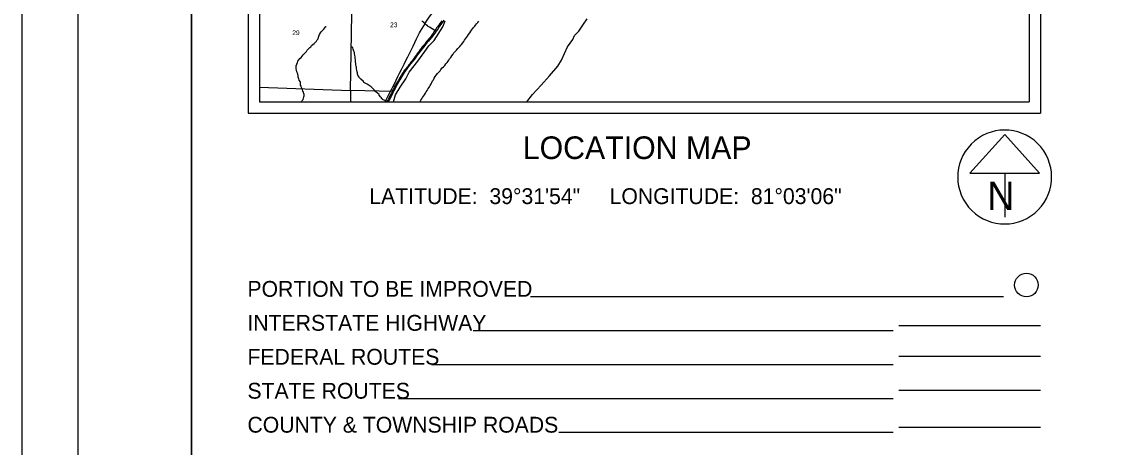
# Model space of a CAD drawing. Extents: x 6.3 to 40.3, y 9 to 31.
# Drawn here: x 6.34 to 15.93, y 20.09 to 23.85 of the extents above; entities that cross this region are included whole.
import ezdxf

# ---------------------------------------------------------------- set-up
doc = ezdxf.new("R2010")
doc.units = 0
for name, color, linetype in [('Default', 7, 'Continuous'), ('GM_X_Corporation', 7, 'Continuous'), ('GM_X_Major_River', 7, 'Continuous'), ('GM_X_Minor_River', 7, 'Continuous'), ('GM_X_Section', 7, 'Continuous'), ('GM_X_Section_Text', 7, 'Continuous'), ('GM_X_State_Route', 7, 'Continuous'), ('SH_Border', 7, 'Continuous'), ('SH_Cut_Line', 7, 'Continuous'), ('SH_Data', 7, 'Continuous'), ('SH_Text', 7, 'Continuous'), ('TX_P_1', 7, 'Continuous')]:
    doc.layers.add(name, color=color, linetype=linetype)

msp = doc.modelspace()

# ---------------------------------------------------------------- linework, layer by layer
at = {"layer": 'Default'}
for points in [[(8.4446, 29.2958), (8.4446, 23.1457), (9.6289, 23.1457), (9.6466, 23.2068), (9.687, 23.2757), (9.738, 23.3494), (9.7691, 23.406), (9.8432, 23.5031), (9.9069, 23.5887), (9.9412, 23.6381), (9.9898, 23.6859), (10.0659, 23.8074), (10.0861, 23.8612)], [(8.4446, 27.9161), (8.4446, 23.1457), (10.8069, 23.1457), (10.8571, 23.2092), (10.9329, 23.292), (11.0065, 23.374), (11.0812, 23.4594), (11.1145, 23.5142), (11.1652, 23.6315), (11.2128, 23.696), (11.2298, 23.7308), (11.2664, 23.7701), (11.3069, 23.8314), (11.3415, 23.8775)]]:
    msp.add_lwpolyline(points, dxfattribs=at)
at = {"layer": 'GM_X_Corporation'}
for points in [[(8.4446, 24.2863), (8.4446, 23.273), (9.2503, 23.246), (9.2683, 24.2583)], [(9.2488, 23.1457), (9.5854, 23.1457), (9.5902, 23.1555), (9.5968, 23.1674), (9.6166, 23.2079), (9.6287, 23.2365), (9.2503, 23.246)]]:
    msp.add_lwpolyline(points, close=True, dxfattribs=at)
at = {"layer": 'GM_X_Major_River'}
for points in [[(10.0561, 23.8618), (10.0461, 23.8476), (10.0391, 23.8354), (10.0303, 23.8223), (10.0187, 23.8081), (10.0102, 23.7981), (10.0043, 23.7877), (9.9947, 23.7754), (9.9858, 23.7624), (9.9799, 23.7524), (9.9706, 23.7386), (9.961, 23.7241), (9.9499, 23.711), (9.9398, 23.6998), (9.9313, 23.6891), (9.9209, 23.6783), (9.9138, 23.6687), (9.9065, 23.6553), (9.8953, 23.6422), (9.8838, 23.6295), (9.8727, 23.6172), (9.8645, 23.606), (9.8564, 23.5937), (9.8479, 23.5811), (9.8397, 23.5711), (9.8312, 23.5592), (9.8204, 23.5465), (9.8145, 23.5365), (9.8094, 23.527), (9.8008, 23.5166), (9.793, 23.5062), (9.7823, 23.4939), (9.773, 23.4801), (9.7619, 23.4678), (9.7548, 23.4578), (9.7463, 23.447), (9.7378, 23.4359), (9.7277, 23.4251), (9.7203, 23.4147), (9.7133, 23.4032), (9.7041, 23.3891), (9.6978, 23.3772), (9.6882, 23.3626), (9.6823, 23.353), (9.6775, 23.3435), (9.6694, 23.3297), (9.6584, 23.3128), (9.6498, 23.3013), (9.6429, 23.2879), (9.6362, 23.2768), (9.6322, 23.2657), (9.6271, 23.2535), (9.6212, 23.2439), (9.6165, 23.2344), (9.611, 23.2218), (9.6036, 23.2076), (9.5974, 23.1965), (9.5915, 23.1851), (9.5842, 23.1694), (9.5776, 23.1571), (9.5732, 23.1472), (9.5724, 23.1457)], [(9.8656, 23.1457), (9.8664, 23.1474), (9.8719, 23.1581), (9.8792, 23.1711), (9.8859, 23.1822), (9.8947, 23.196), (9.9025, 23.2071), (9.911, 23.2205), (9.9191, 23.2328), (9.9269, 23.2455), (9.9339, 23.2577), (9.9402, 23.2673), (9.9468, 23.278), (9.9546, 23.2888), (9.963, 23.3037), (9.9685, 23.3167), (9.9751, 23.3289), (9.9814, 23.3397), (9.9884, 23.3527), (9.9983, 23.3688), (10.0076, 23.3814), (10.0195, 23.3945), (10.0288, 23.4057), (10.0422, 23.4199), (10.0481, 23.4299), (10.0604, 23.4441), (10.0704, 23.4549), (10.0816, 23.4669), (10.0908, 23.4795), (10.102, 23.4922), (10.1109, 23.503), (10.1187, 23.513), (10.1246, 23.5233), (10.1353, 23.5368), (10.1457, 23.5521), (10.1561, 23.566), (10.1631, 23.5763), (10.1742, 23.5894), (10.1862, 23.6017), (10.1988, 23.6152), (10.2141, 23.6322), (10.2249, 23.6441), (10.2319, 23.6537), (10.2404, 23.6637), (10.2501, 23.6771), (10.2571, 23.689), (10.2652, 23.7009), (10.2733, 23.7136), (10.2826, 23.7255), (10.2933, 23.7408), (10.3048, 23.755), (10.3126, 23.7685), (10.3189, 23.7784), (10.3259, 23.7888), (10.337, 23.8011), (10.3475, 23.8126), (10.3541, 23.8222), (10.3626, 23.8334), (10.3734, 23.8446), (10.3823, 23.8576)]]:
    msp.add_lwpolyline(points, dxfattribs=at)
at = {"layer": 'GM_X_Minor_River'}
for points in [[(8.9836, 23.7535), (8.9913, 23.764), (9.0048, 23.7774), (9.0148, 23.7871), (9.0215, 23.7988), (9.0311, 23.8089), (9.0338, 23.8115)], [(9.9947, 23.7754), (9.9481, 23.8036), (9.9361, 23.81), (9.9286, 23.8158), (9.9172, 23.8245), (9.9152, 23.8275), (9.9056, 23.837), (9.8982, 23.8421), (9.8969, 23.8451), (9.8883, 23.8516), (9.8809, 23.8566)], [(8.8177, 23.1457), (8.8233, 23.1554), (8.83, 23.1663), (8.8339, 23.1776), (8.8371, 23.1878), (8.8392, 23.1987), (8.8398, 23.2082), (8.8384, 23.2181), (8.8348, 23.2291), (8.8297, 23.2398), (8.8253, 23.2502), (8.8217, 23.2597), (8.817, 23.2708), (8.8122, 23.2834), (8.809, 23.2933), (8.8069, 23.3035), (8.8063, 23.3157), (8.8035, 23.3256), (8.7972, 23.3352), (8.7925, 23.3474), (8.7882, 23.3638), (8.7873, 23.3744), (8.7852, 23.3881), (8.7812, 23.3988), (8.7765, 23.4106), (8.771, 23.4247), (8.7694, 23.4373), (8.7705, 23.4619), (8.7746, 23.4778), (8.7798, 23.4925), (8.7845, 23.503), (8.7931, 23.5158), (8.8023, 23.5262), (8.8127, 23.5363), (8.8217, 23.5483), (8.8313, 23.5591), (8.841, 23.5689), (8.8502, 23.5786), (8.8606, 23.5894), (8.8677, 23.6025), (8.8773, 23.6138), (8.8896, 23.6238), (8.8996, 23.6316), (8.9055, 23.6418), (8.9167, 23.6526), (8.9282, 23.66), (8.9386, 23.6697), (8.9479, 23.6813), (8.9564, 23.6918), (8.963, 23.7023), (8.9674, 23.7155), (8.9706, 23.7257), (8.9769, 23.7403), (8.9836, 23.7535)], [(9.5732, 23.1472), (9.5319, 23.1667), (9.531, 23.1697), (9.524, 23.1743), (9.5219, 23.1788), (9.5131, 23.188), (9.504, 23.2052), (9.5022, 23.2108), (9.4885, 23.221), (9.4864, 23.2243), (9.4767, 23.2304), (9.4656, 23.2391), (9.4639, 23.244), (9.4527, 23.2577), (9.4463, 23.2635), (9.4313, 23.2778), (9.4231, 23.2828), (9.4066, 23.2951), (9.3973, 23.2997), (9.367, 23.3165), (9.3629, 23.324), (9.3403, 23.3452), (9.3277, 23.3557), (9.3251, 23.3629), (9.3147, 23.3815), (9.3113, 23.3894), (9.31, 23.4015), (9.3082, 23.4087), (9.3055, 23.4249), (9.3038, 23.437), (9.3012, 23.4525), (9.2993, 23.4597), (9.2973, 23.4718), (9.2957, 23.4816), (9.2937, 23.4998), (9.2931, 23.5131), (9.2919, 23.5294), (9.2896, 23.5392), (9.2872, 23.557), (9.2855, 23.5688), (9.2835, 23.5801), (9.2809, 23.5872), (9.2794, 23.5937), (9.2741, 23.6102), (9.2709, 23.6223), (9.2673, 23.6259), (9.2653, 23.6289), (9.264, 23.6327)]]:
    msp.add_lwpolyline(points, dxfattribs=at)
at = {"layer": 'GM_X_Section'}
msp.add_lwpolyline([(10.0745, 23.867), (10.0585, 23.8459), (10.0463, 23.8271), (10.0356, 23.8122), (10.0227, 23.7915), (10.0015, 23.7609), (9.9674, 23.7171), (9.948, 23.6937), (9.9373, 23.6803), (9.9157, 23.6545), (9.9049, 23.6434), (9.8819, 23.6142), (9.8477, 23.5678), (9.8255, 23.5383), (9.8151, 23.5226), (9.798, 23.5022), (9.769, 23.465), (9.7338, 23.4163), (9.7238, 23.4032), (9.7134, 23.3883), (9.6842, 23.3393), (9.6603, 23.2973), (9.639, 23.2533), (9.6324, 23.2403), (9.6287, 23.2365), (9.2503, 23.246), (9.2683, 24.2583)], dxfattribs=at)
at = {"layer": 'GM_X_State_Route'}
for points in [[(9.7553, 23.5432), (9.7643, 23.5614), (9.7815, 23.5958), (9.8021, 23.6369), (9.8337, 23.7003), (9.8605, 23.7536), (9.8693, 23.7701), (9.8821, 23.7928), (9.8967, 23.8174), (9.912, 23.8424), (9.9211, 23.8564), (9.9397, 23.8836), (9.9539, 23.9041), (9.9671, 23.9222), (9.9777, 23.936), (9.9958, 23.9589), (10.0097, 23.9756), (10.0207, 23.9882)], [(9.5566, 23.1457), (9.5597, 23.1518), (9.571, 23.1746), (9.5827, 23.198), (9.598, 23.2285), (9.611, 23.2546), (9.6257, 23.2834), (9.6368, 23.3049), (9.6533, 23.3376), (9.6682, 23.3677), (9.6835, 23.3982), (9.6997, 23.4304), (9.7225, 23.4767), (9.7357, 23.5034), (9.7553, 23.5432)]]:
    msp.add_lwpolyline(points, dxfattribs=at)
at = {"layer": 'SH_Border'}
for points in [[(6.8446, 30.5457), (7.8446, 30.5457), (7.8446, 9.5457), (6.8446, 9.5457)], [(7.8446, 30.5457), (39.8446, 30.5457), (39.8446, 9.5457), (7.8446, 9.5457)]]:
    msp.add_lwpolyline(points, close=True, dxfattribs=at)
at = {"layer": 'SH_Cut_Line'}
msp.add_lwpolyline([(6.3446, 9.0457), (40.3446, 9.0457), (40.3446, 31.0457), (6.3446, 31.0457)], close=True, dxfattribs=at)
msp.add_lwpolyline([(8.4446, 29.2958), (8.4446, 23.1457), (9.6289, 23.1457), (9.6466, 23.2068), (9.687, 23.2757), (9.738, 23.3494), (9.7691, 23.406), (9.8432, 23.5031), (9.9069, 23.5887), (9.9412, 23.6381), (9.9898, 23.6859), (10.0659, 23.8074), (10.0861, 23.8612)], dxfattribs=at)
at = {"layer": 'SH_Data'}
for p, q in [((8.3446, 30.0457), (8.3446, 23.0457)), ((15.3446, 30.0457), (15.3446, 23.0457)), ((8.4446, 29.9457), (8.4446, 23.1457)), ((15.2446, 29.9457), (15.2446, 23.1457)), ((8.4446, 23.1457), (15.2446, 23.1457)), ((8.3446, 23.0457), (15.3446, 23.0457)), ((15.0291, 22.8548), (14.7215, 22.5135)), ((15.3367, 22.5135), (15.0291, 22.8548)), ((14.7215, 22.5135), (15.3367, 22.5135)), ((15.0291, 22.5135), (15.0291, 22.1268)), ((15.0291, 22.481), (15.0291, 22.481)), ((15.0291, 22.481), (15.0291, 22.481)), ((15.0183, 21.4224), (10.8383, 21.4224)), ((14.0446, 21.1224), (10.3341, 21.1224)), ((15.3446, 21.1665), (14.0946, 21.1665)), ((15.3446, 20.8948), (14.0946, 20.8948)), ((14.0446, 20.8224), (9.9638, 20.8224)), ((14.0446, 20.5224), (9.6734, 20.5224)), ((15.3446, 20.5948), (14.0946, 20.5948)), ((14.0446, 20.2224), (11.0899, 20.2224)), ((15.3446, 20.268), (14.0946, 20.268))]:
    msp.add_line(p, q, dxfattribs=at)
msp.add_arc((15.0291, 22.481), 0.4148, 129.77984, 129.76332, dxfattribs=at)
at = {"layer": 'TX_P_1'}
msp.add_circle((15.2208, 21.5265), 0.1042, dxfattribs=at)

# ---------------------------------------------------------------- texts
at = {"layer": 'GM_X_Section_Text'}
for s, p in [('29', (8.7356, 23.7343)), ('23', (9.5998, 23.8043))]:
    msp.add_text(s, height=0.04186, rotation=0.00001, dxfattribs=at).set_placement(p)
at = {"layer": 'SH_Data'}
msp.add_text('N', height=0.25, dxfattribs=at).set_placement((14.8738, 22.1897))
at = {"layer": 'SH_Text'}
for s, height, p in [('LOCATION MAP', 0.2, (10.7715, 22.6395)), ('LATITUDE:  39°31\'54"     LONGITUDE:  81°03\'06"', 0.14, (9.4156, 22.2416)), ('PORTION TO BE IMPROVED', 0.14, (8.339, 21.4224)), ('INTERSTATE HIGHWAY', 0.14, (8.339, 21.1224)), ('FEDERAL ROUTES', 0.14, (8.339, 20.8224)), ('STATE ROUTES', 0.14, (8.339, 20.5224)), ('COUNTY & TOWNSHIP ROADS', 0.14, (8.339, 20.2224))]:
    msp.add_text(s, height=height, dxfattribs=at).set_placement(p)

doc.saveas('drawing.dxf')
